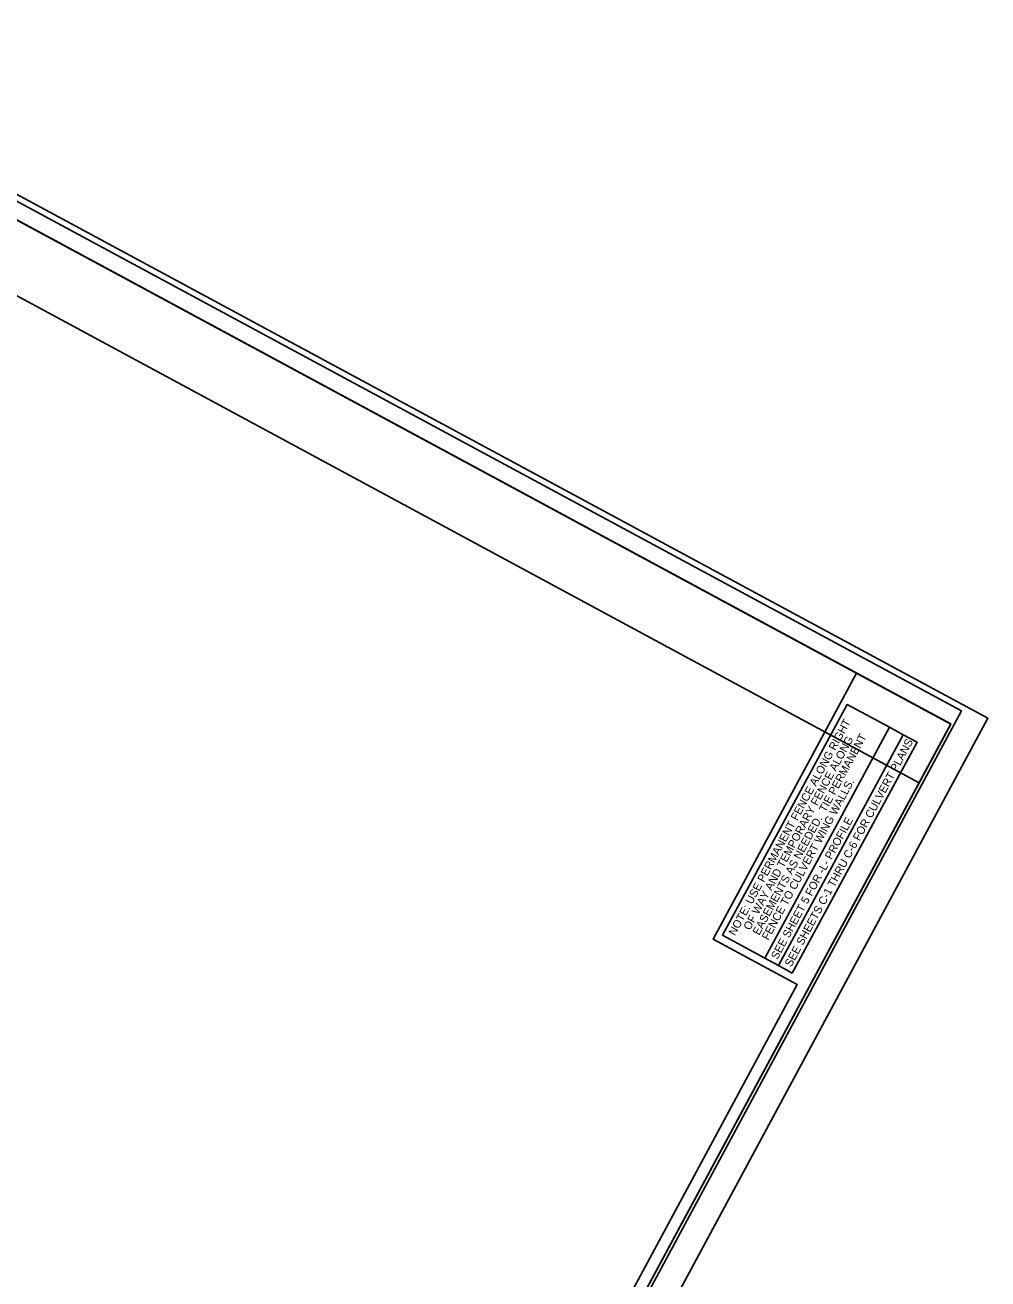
# Model space of a CAD drawing. Extents: x 1376633 to 1377691, y 762405 to 763679.
# Drawn here: x 1377258 to 1377691, y 763042 to 763606 of the extents above; entities that cross this region are included whole.
import ezdxf

# ---------------------------------------------------------------- set-up
doc = ezdxf.new("R2010")
doc.units = 0
for name, color, linetype in [('Prop DSN Text', 7, 'Continuous'), ('Prop Grid Mask', 7, 'Continuous'), ('Sheet Clip Boundary CELL', 7, 'Continuous'), ('Sheet Cutting Line CELL', 7, 'Continuous'), ('Sheet Layout Plan Border', 7, 'Continuous'), ('Sheet Plan CELL', 7, 'Continuous'), ('Sheet Plan Layout CELL', 7, 'Continuous'), ('Sheet Plot Border Inside CELL', 7, 'Continuous'), ('Sheet Plot Border Outside CELL', 7, 'Continuous')]:
    doc.layers.add(name, color=color, linetype=linetype)

msp = doc.modelspace()

# ---------------------------------------------------------------- linework, layer by layer
at = {"layer": 'Prop Grid Mask'}
for points in [[(1377590.62, 763186.18), (1377646.8, 763289.97), (1377627.8, 763300.26), (1377571.62, 763196.46)], [(1377596.84, 763182.8), (1377653.02, 763286.6), (1377646.8, 763289.97), (1377590.62, 763186.17)], [(1377603.03, 763179.45), (1377659.22, 763283.25), (1377653.02, 763286.6), (1377596.84, 763182.8)]]:
    msp.add_lwpolyline(points, close=True, dxfattribs=at)
at = {"layer": 'Sheet Clip Boundary CELL'}
msp.add_lwpolyline([(1377242.74, 762501.71), (1377605.3, 763174.23), (1377567.4, 763194.66), (1377631.93, 763314.35), (1377205.29, 763544.36), (1377145.3, 763433.08), (1377063.51, 763477.17), (1376696.41, 762796.24)], close=True, dxfattribs=at)
at = {"layer": 'Sheet Cutting Line CELL'}
msp.add_line((1377211.77, 762404.92), (1377691.11, 763294.04), dxfattribs=at)
at = {"layer": 'Sheet Layout Plan Border'}
msp.add_lwpolyline([(1377261.52, 762525.66), (1377660.14, 763265.06), (1377217.29, 763503.81), (1377163.4, 763403.85), (1377051.71, 763464.07), (1376706.97, 762824.63)], close=True, dxfattribs=at)
at = {"layer": 'Sheet Plan CELL'}
for points in [[(1377119.84, 763590.45), (1376692.74, 762798.22), (1377247.28, 762499.26), (1377674.38, 763291.47)], [(1377247.28, 762499.26), (1376692.74, 762798.2), (1377062.86, 763484.78), (1377142.12, 763442.06), (1377199.08, 763547.71), (1377674.38, 763291.47)]]:
    msp.add_lwpolyline(points, close=True, dxfattribs=at)
at = {"layer": 'Sheet Plan Layout CELL'}
msp.add_lwpolyline([(1376692.74, 762798.2), (1377247.28, 762499.26), (1377674.37, 763291.46), (1377231.52, 763530.21), (1377163.4, 763403.85), (1377051.71, 763464.07)], close=True, dxfattribs=at)
at = {"layer": 'Sheet Plot Border Inside CELL'}
msp.add_lwpolyline([(1377204.91, 762417.48), (1377679.25, 763297.35), (1377122.08, 763597.74), (1376647.72, 762717.87)], close=True, dxfattribs=at)
at = {"layer": 'Sheet Plot Border Outside CELL'}
msp.add_lwpolyline([(1377211.77, 762404.92), (1377691.11, 763294.04), (1377112.79, 763605.82), (1376633.46, 762716.69)], close=True, dxfattribs=at)

# ---------------------------------------------------------------- texts
at = {"layer": 'Prop DSN Text'}
for s, p in [('NOTE: USE PERMANENT FENCE ALONG RIGHT', (1377577.28, 763195.98)), ('    EASEMENTS AS NEEDED.  TIE PERMANENT', (1377585.58, 763191.48)), ('    OF WAY AND TEMPORARY FENCE ALONG', (1377581.43, 763193.73)), ('SEE SHEETS C-1 THRU C-6 FOR CULVERT PLANS', (1377602.57, 763181.94)), ('    FENCE TO CULVERT WING WALLS.', (1377589.73, 763189.24)), ('SEE SHEET 5 FOR -L- PROFILE', (1377596.38, 763185.29))]:
    msp.add_text(s, height=3.6, rotation=61.5755, dxfattribs=at).set_placement(p)

doc.saveas('drawing.dxf')
